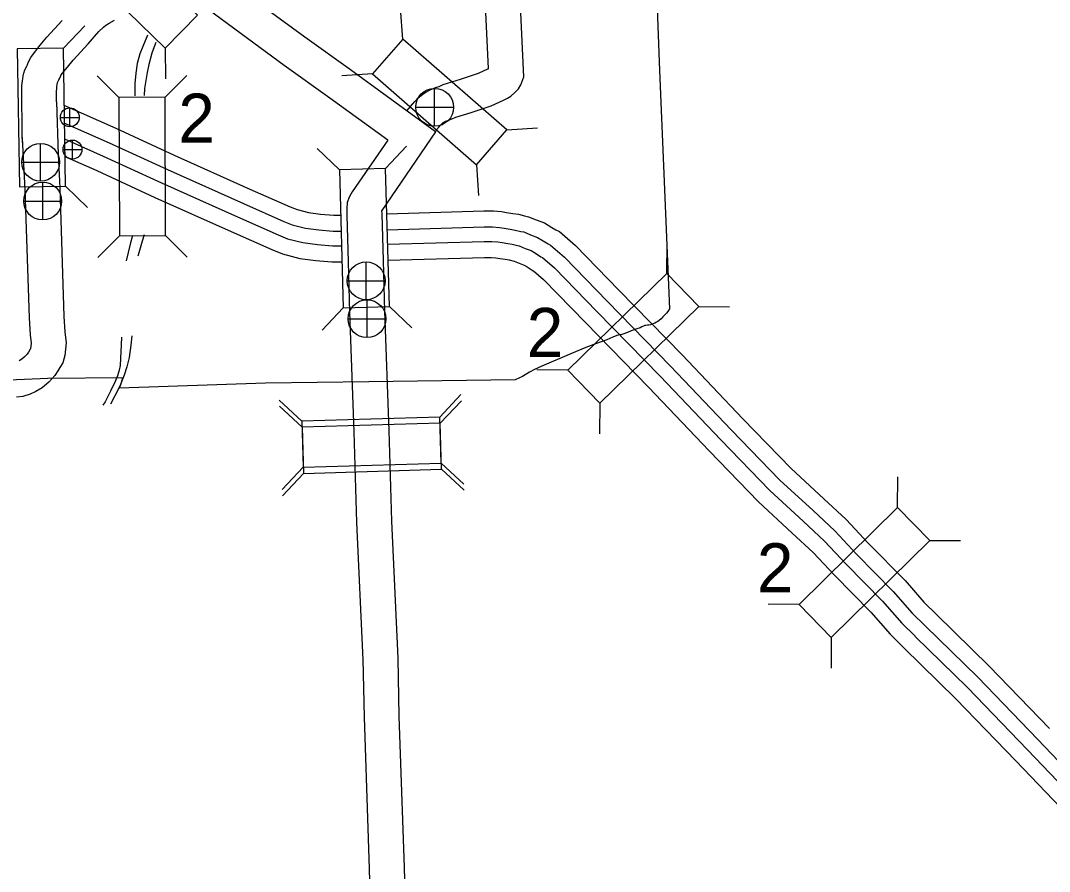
# Model space of a CAD drawing. Extents: x -117616 to 64730, y 54117 to 789866.
# Drawn here: x 61631.6 to 61720, y 55902.9 to 55976 of the extents above; entities that cross this region are included whole.
import ezdxf

# ---------------------------------------------------------------- set-up
doc = ezdxf.new("R2010")
doc.units = 0
for name, color, linetype in [('Level 10', 7, 'Continuous'), ('Level 15', 7, 'Continuous'), ('Level 19', 7, 'Continuous'), ('Level 20', 7, 'Continuous'), ('Level 26', 7, 'Continuous'), ('Level 6', 7, 'Continuous'), ('Level 9', 7, 'Continuous')]:
    doc.layers.add(name, color=color, linetype=linetype)

msp = doc.modelspace()

# ---------------------------------------------------------------- linework, layer by layer
at = {"layer": 'Level 10'}
for points in [[(61671.813, 55971.825), (61671.216, 55984.46)], [(61674.849, 55971.134), (61674.214, 55984.588)], [(61664.793, 55968.204), (61665.296, 55968.781), (61665.489, 55969.007), (61665.697, 55969.212), (61665.757, 55969.275), (61666.046, 55969.558), (61666.38, 55969.768), (61666.527, 55969.86), (61666.815, 55970.012), (61667.081, 55970.132), (61667.275, 55970.192), (61667.579, 55970.302), (61667.922, 55970.466), (61669.407, 55970.919), (61670.95, 55971.442), (61671.752, 55971.797), (61671.773, 55971.803), (61671.813, 55971.825)], [(61667.248, 55966.409), (61667.342, 55966.563), (61667.568, 55966.821), (61667.688, 55966.962), (61667.833, 55967.105), (61667.89, 55967.165), (61667.915, 55967.189), (61667.976, 55967.228), (61668.026, 55967.259), (61668.134, 55967.316), (61668.145, 55967.321), (61668.229, 55967.347), (61668.74, 55967.532), (61669.011, 55967.662), (61670.327, 55968.063), (61672.04, 55968.644), (61673.111, 55969.118), (61673.434, 55969.288), (61673.745, 55969.471), (61674.087, 55969.771), (61674.256, 55969.948), (61674.379, 55970.101), (61674.602, 55970.423), (61674.849, 55971.134)], [(61631.766, 55965.82), (61631.742, 55970.357)], [(61634.693, 55968.979), (61634.838, 55964.44)], [(61631.766, 55965.82), (61631.982, 55961.455), (61632.351, 55950.405), (61632.435, 55948.962), (61632.519, 55948.23), (61632.473, 55947.763), (61632.471, 55947.757), (61632.448, 55947.717), (61632.292, 55947.469), (61632.179, 55947.294), (61631.968, 55947.063), (61631.738, 55946.87), (61631.487, 55946.723)], [(61663.181, 55965.668), (61660.102, 55961.245), (61659.878, 55960.847), (61659.673, 55960.329), (61659.637, 55959.771), (61659.638, 55959.238), (61659.758, 55955.213)], [(61667.248, 55966.409), (61662.647, 55959.65), (61662.637, 55959.632), (61662.638, 55959.351), (61662.755, 55955.355)], [(61634.838, 55964.44), (61634.98, 55961.579), (61635.348, 55950.543), (61635.425, 55949.221), (61635.536, 55948.254), (61635.431, 55947.188), (61635.241, 55946.542), (61635.005, 55946.149), (61634.824, 55945.86), (61634.564, 55945.457), (61634.05, 55944.893), (61633.471, 55944.408), (61632.943, 55944.099), (61632.456, 55943.843), (61631.816, 55943.668), (61631.272, 55943.588)], [(61659.758, 55955.213), (61659.886, 55950.897), (61660.25, 55940.627), (61660.485, 55932.825), (61661.016, 55921.045)], [(61662.755, 55955.355), (61662.884, 55950.995), (61663.248, 55940.725), (61663.483, 55932.938), (61664.012, 55921.18)], [(61661.014, 55921.08), (61661.121, 55916.106), (61661.57, 55903.085), (61661.891, 55891.66), (61662.566, 55872.326), (61663.298, 55855.181), (61664.096, 55835.524), (61664.175, 55832.474), (61664.219, 55831.429), (61664.111, 55828.639), (61663.971, 55824.356), (61663.848, 55819.642), (61663.828, 55816.991), (61663.925, 55813.269), (61663.931, 55812.339), (61663.933, 55812.326)], [(61664.014, 55921.145), (61664.12, 55916.19), (61664.568, 55903.179), (61664.89, 55891.755), (61665.564, 55872.443), (61666.296, 55855.306), (61667.095, 55835.624), (61667.173, 55832.576), (61667.221, 55831.435), (61667.109, 55828.532), (61666.97, 55824.268), (61666.848, 55819.592), (61666.829, 55817.019), (61666.925, 55813.318), (61666.93, 55812.561), (61666.956, 55812.374)]]:
    msp.add_lwpolyline(points, dxfattribs=at)
at = {"layer": 'Level 15'}
for points in [[(61667.248, 55966.409), (61659.949, 55971.71), (61656.025, 55974.518), (61649.047, 55979.666), (61647.318, 55980.868), (61646.593, 55981.352), (61646.235, 55981.563), (61645.835, 55981.85), (61643.674, 55983.76)], [(61663.181, 55965.668), (61658.196, 55969.275), (61654.261, 55972.092), (61647.3, 55977.227), (61645.629, 55978.388), (61644.996, 55978.811), (61644.595, 55979.048), (61643.963, 55979.5), (61643.946, 55979.516), (61643.853, 55979.421)], [(61631.742, 55970.357), (61631.742, 55970.358), (61631.762, 55970.554), (61631.788, 55970.801), (61631.8, 55970.919), (61631.847, 55971.222), (61631.909, 55971.434), (61631.973, 55971.714), (61632.144, 55972.029), (61632.206, 55972.145), (61632.218, 55972.174), (61632.313, 55972.4), (61632.505, 55972.788), (61632.808, 55973.206), (61633.308, 55973.848), (61633.884, 55974.536), (61635.186, 55975.957)], [(61634.693, 55968.979), (61634.692, 55969.409), (61634.696, 55969.464), (61634.706, 55969.636), (61634.711, 55969.831), (61634.716, 55969.888), (61634.732, 55970.105), (61634.746, 55970.251), (61634.771, 55970.487), (61634.776, 55970.53), (61634.782, 55970.569), (61634.801, 55970.635), (61634.92, 55970.861), (61634.984, 55971.013), (61635.042, 55971.152), (61635.081, 55971.23), (61635.206, 55971.403), (61635.643, 55971.963), (61636.142, 55972.56), (61637.424, 55973.959), (61638.345, 55975.018), (61638.748, 55975.396), (61638.943, 55975.564), (61638.995, 55975.599), (61639.219, 55975.729), (61639.7, 55975.992)], [(61631.805, 55965.031), (61631.776, 55965.905)]]:
    msp.add_lwpolyline(points, dxfattribs=at)
at = {"layer": 'Level 19'}
for points in [[(61635.343, 55968.676), (61639.807, 55966.713), (61644.799, 55964.405), (61651.324, 55961.483), (61654.774, 55959.966), (61655.387, 55959.71), (61656.356, 55959.46), (61657.395, 55959.332), (61658.515, 55959.236), (61659.119, 55959.237)], [(61635.338, 55967.177), (61639.242, 55965.459), (61644.23, 55963.154), (61650.766, 55960.226), (61654.232, 55958.702), (61654.949, 55958.403), (61656.099, 55958.107), (61657.252, 55957.964), (61658.457, 55957.861), (61659.157, 55957.862)], [(61635.388, 55965.789), (61638.728, 55964.32), (61643.712, 55962.016), (61650.259, 55959.083), (61653.74, 55957.553), (61654.55, 55957.215), (61655.865, 55956.876), (61657.122, 55956.721), (61658.404, 55956.611), (61659.192, 55956.612)], [(61635.423, 55964.272), (61638.163, 55963.066), (61643.143, 55960.765), (61649.701, 55957.826), (61653.198, 55956.289), (61654.111, 55955.909), (61655.608, 55955.522), (61656.979, 55955.353), (61658.345, 55955.236), (61659.231, 55955.237)], [(61663.077, 55959.362), (61671.408, 55959.61), (61672.241, 55959.61), (61672.918, 55959.539), (61673.36, 55959.479), (61673.901, 55959.394), (61674.385, 55959.309), (61674.913, 55959.187), (61675.263, 55959.105), (61675.912, 55958.831), (61676.625, 55958.572), (61677.25, 55958.187), (61677.591, 55957.971), (61677.904, 55957.822), (61679.284, 55956.623), (61683.003, 55952.796), (61688.44, 55947.228), (61693.658, 55941.747), (61697.81, 55937.465), (61700.626, 55934.861), (61702.532, 55933.085), (61704.428, 55931.065), (61707.592, 55927.849), (61709.222, 55925.975), (61710.293, 55924.925)], [(61663.115, 55957.988), (61671.428, 55958.235), (61672.169, 55958.235), (61672.753, 55958.174), (61673.161, 55958.118), (61673.676, 55958.038), (61674.111, 55957.961), (61674.602, 55957.847), (61674.836, 55957.793), (61675.41, 55957.551), (61676.023, 55957.328), (61676.522, 55957.02), (61676.926, 55956.766), (61677.143, 55956.662), (61678.338, 55955.623), (61682.018, 55951.836), (61687.45, 55946.274), (61692.667, 55940.794), (61696.849, 55936.481), (61699.691, 55933.853), (61701.561, 55932.11), (61703.436, 55930.112), (61706.582, 55926.915), (61708.22, 55925.032), (61709.33, 55923.943)], [(61663.15, 55956.738), (61671.447, 55956.985), (61672.104, 55956.985), (61672.604, 55956.932), (61672.98, 55956.881), (61673.471, 55956.804), (61673.861, 55956.736), (61674.319, 55956.63), (61674.448, 55956.6), (61674.953, 55956.387), (61675.477, 55956.197), (61675.861, 55955.96), (61676.32, 55955.669), (61676.45, 55955.607), (61677.478, 55954.714), (61681.123, 55950.964), (61686.55, 55945.406), (61691.765, 55939.928), (61695.976, 55935.586), (61698.84, 55932.937), (61700.678, 55931.224), (61702.535, 55929.246), (61705.664, 55926.066), (61707.309, 55924.174), (61708.454, 55923.051)], [(61663.189, 55955.364), (61671.468, 55955.61), (61672.033, 55955.61), (61672.44, 55955.567), (61672.781, 55955.521), (61673.246, 55955.448), (61673.587, 55955.388), (61674.008, 55955.291), (61674.022, 55955.287), (61674.451, 55955.106), (61674.875, 55954.952), (61675.133, 55954.793), (61675.655, 55954.464), (61675.689, 55954.447), (61676.532, 55953.714), (61680.138, 55950.004), (61685.56, 55944.452), (61690.774, 55938.975), (61695.015, 55934.602), (61697.905, 55931.929), (61699.707, 55930.25), (61701.543, 55928.293), (61704.654, 55925.132), (61706.307, 55923.231), (61707.491, 55922.069)], [(61710.291, 55924.926), (61714.811, 55920.501), (61719.994, 55915.135)], [(61709.329, 55923.944), (61713.835, 55919.532), (61719.005, 55914.18)], [(61708.455, 55923.05), (61712.948, 55918.651), (61718.106, 55913.311)], [(61707.493, 55922.068), (61711.972, 55917.682), (61717.117, 55912.356)], [(61719.007, 55914.178), (61726.143, 55906.722)], [(61718.104, 55913.313), (61725.184, 55905.916)], [(61717.111, 55912.363), (61724.191, 55904.965)]]:
    msp.add_lwpolyline(points, dxfattribs=at)
at = {"layer": 'Level 20'}
for p, q in [((61664.446, 55974.371), (61664.268, 55977.005)), ((61635.299, 55973.599), (61637.137, 55975.494)), ((61644.04, 55973.585), (61644.071, 55970.945)), ((61640.071, 55969.349), (61638.198, 55971.21)), ((61644.031, 55969.362), (61645.891, 55971.235)), ((61661.841, 55971.389), (61659.207, 55971.211)), ((61673.393, 55966.555), (61676.027, 55966.733)), ((61659.01, 55963.143), (61657.091, 55964.957)), ((61662.968, 55963.254), (61664.782, 55965.172)), ((61670.788, 55963.573), (61670.965, 55960.939)), ((61635.482, 55961.72), (61637.377, 55959.882)), ((61640.111, 55957.469), (61638.25, 55955.596)), ((61644.071, 55957.482), (61645.944, 55955.622)), ((61687.119, 55954.22), (61687.15, 55956.86)), ((61659.342, 55951.268), (61657.528, 55949.35)), ((61663.301, 55951.379), (61665.219, 55949.565)), ((61689.885, 55951.387), (61692.525, 55951.356)), ((61678.619, 55945.92), (61675.979, 55945.951)), ((61667.641, 55941.893), (61669.451, 55943.815)), ((61655.766, 55941.536), (61653.844, 55943.345)), ((61655.796, 55941.012), (61653.874, 55942.821)), ((61667.671, 55941.369), (61669.481, 55943.291)), ((61681.386, 55943.087), (61681.354, 55940.447)), ((61655.885, 55937.577), (61654.076, 55935.655)), ((61667.696, 55937.933), (61667.76, 55937.935)), ((61667.76, 55937.935), (61669.682, 55936.125)), ((61667.79, 55937.411), (61669.712, 55935.601)), ((61655.915, 55937.053), (61654.106, 55935.131)), ((61706.954, 55934.115), (61706.975, 55936.755)), ((61709.731, 55931.292), (61712.371, 55931.271)), ((61698.486, 55925.783), (61695.846, 55925.804)), ((61701.263, 55922.96), (61701.242, 55920.32))]:
    msp.add_line(p, q, dxfattribs=at)
for points in [[(61646.807, 55976.418), (61638.309, 55984.719), (61635.542, 55981.886), (61644.04, 55973.585)], [(61673.393, 55966.555), (61664.446, 55974.371), (61661.841, 55971.389), (61670.788, 55963.573)], [(61635.482, 55961.72), (61635.299, 55973.599), (61631.339, 55973.538), (61631.522, 55961.659)], [(61644.071, 55957.482), (61644.031, 55969.362), (61640.071, 55969.349), (61640.111, 55957.469)], [(61663.301, 55951.379), (61662.968, 55963.254), (61659.01, 55963.143), (61659.342, 55951.268)], [(61687.119, 55954.22), (61678.619, 55945.92), (61681.386, 55943.087), (61689.885, 55951.387)], [(61667.641, 55941.893), (61655.766, 55941.536), (61655.885, 55937.577), (61667.76, 55937.935)], [(61667.671, 55941.369), (61655.796, 55941.012), (61655.915, 55937.053), (61667.79, 55937.411)], [(61706.954, 55934.115), (61698.486, 55925.783), (61701.263, 55922.96), (61709.731, 55931.292)]]:
    msp.add_lwpolyline(points, close=True, dxfattribs=at)
at = {"layer": 'Level 26'}
for p, q in [((61667.189, 55966.879), (61667.189, 55970.129)), ((61635.848, 55966.83), (61635.848, 55968.455)), ((61665.564, 55968.504), (61668.814, 55968.504)), ((61635.036, 55967.642), (61636.661, 55967.642)), ((61636.078, 55964.062), (61636.078, 55965.687)), ((61633.343, 55962.155), (61633.343, 55965.405)), ((61635.265, 55964.874), (61636.89, 55964.874)), ((61631.718, 55963.78), (61634.968, 55963.78)), ((61633.52, 55958.826), (61633.52, 55962.076)), ((61631.895, 55960.451), (61635.145, 55960.451)), ((61661.306, 55951.968), (61661.306, 55955.218)), ((61659.681, 55953.593), (61662.931, 55953.593)), ((61661.38, 55948.712), (61661.38, 55951.962)), ((61659.755, 55950.337), (61663.005, 55950.337))]:
    msp.add_line(p, q, dxfattribs=at)
for centre, radius in [((61667.189, 55968.504), 1.625), ((61635.848, 55967.642), 0.812), ((61636.078, 55964.874), 0.812), ((61633.343, 55963.78), 1.625), ((61633.52, 55960.451), 1.625), ((61661.306, 55953.593), 1.625), ((61661.38, 55950.337), 1.625)]:
    msp.add_circle(centre, radius, dxfattribs=at)
at = {"layer": 'Level 6'}
for points in [[(61685.499, 55998.376), (61686.516, 55971.664), (61687.363, 55951.183), (61687.22, 55950.974), (61687.096, 55950.813), (61686.946, 55950.641), (61686.793, 55950.488), (61686.647, 55950.334), (61686.46, 55950.177), (61686.373, 55950.112), (61686.245, 55950.044), (61686.092, 55949.964), (61685.918, 55949.886), (61685.736, 55949.82), (61685.599, 55949.787), (61685.485, 55949.775), (61685.329, 55949.768), (61685.246, 55949.755), (61685.172, 55949.733), (61684.98, 55949.629), (61684.832, 55949.563), (61684.55, 55949.467), (61684.238, 55949.365), (61684.069, 55949.304), (61683.759, 55949.148), (61683.345, 55948.999), (61683.272, 55948.976), (61683.219, 55948.968), (61683.152, 55948.963), (61683.07, 55948.966), (61683.026, 55948.963), (61682.949, 55948.938), (61682.847, 55948.899), (61682.508, 55948.749), (61681.975, 55948.519), (61681.087, 55948.216), (61680.17, 55947.861), (61678.956, 55947.358), (61676.388, 55946.262), (61675.759, 55945.966), (61675.347, 55945.75), (61674.731, 55945.389), (61674.488, 55945.269), (61674.113, 55945.098), (61661.532, 55944.92), (61652.66, 55944.805), (61640.108, 55944.366), (61640.257, 55944.788), (61640.412, 55945.273), (61633.969, 55945.196)], [(61633.969, 55945.196), (61607.718, 55944.08)]]:
    msp.add_lwpolyline(points, dxfattribs=at)
at = {"layer": 'Level 9'}
for points in [[(61642.521, 55974.705), (61642.473, 55974.553), (61642.111, 55973.714), (61641.868, 55973.111), (61641.645, 55972.277), (61641.522, 55971.448), (61641.431, 55970.55), (61641.421, 55969.488)], [(61643.234, 55974.068), (61643.091, 55973.686), (61642.895, 55973.145), (61642.647, 55972.19), (61642.488, 55971.5), (61642.379, 55970.813), (61642.27, 55970.115), (61642.241, 55969.517)], [(61641.226, 55957.476), (61641.033, 55956.742), (61640.684, 55955.302)], [(61642.231, 55957.543), (61642.071, 55956.998), (61641.775, 55956.011), (61641.7, 55955.703)], [(61641.177, 55948.883), (61641.087, 55948.076), (61640.934, 55947.005), (61640.75, 55946.193), (61640.512, 55945.49), (61640.144, 55944.55), (61639.711, 55943.717), (61639.331, 55942.995)], [(61640.282, 55948.76), (61640.267, 55948.091), (61640.199, 55946.923), (61640.166, 55946.319), (61640.083, 55945.933), (61639.935, 55945.425), (61639.757, 55944.945), (61639.354, 55944.124), (61638.875, 55943.209), (61638.694, 55942.914)]]:
    msp.add_lwpolyline(points, dxfattribs=at)

# ---------------------------------------------------------------- texts
at = {"layer": 'Level 20'}
for p in [(61645.164, 55965.457), (61675.099, 55947.044), (61694.868, 55926.824)]:
    msp.add_text('2', height=4.224, dxfattribs=at).set_placement(p)

doc.saveas('drawing.dxf')
